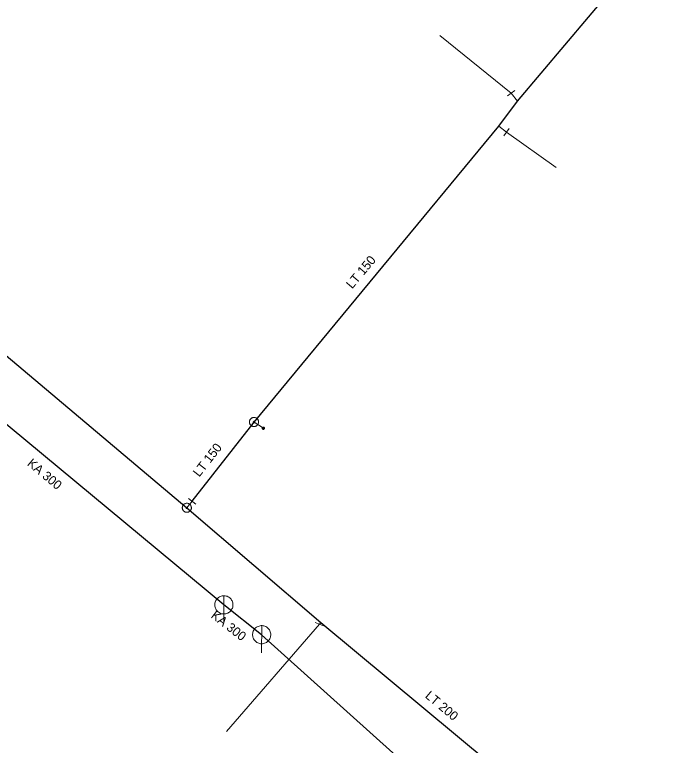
# Model space of a CAD drawing. Extents: x -790267 to -789874, y -989766 to -989454.
# Drawn here: x -790122.7 to -790051.8, y -989692.4 to -989612.1 of the extents above; entities that cross this region are included whole.
import ezdxf

# ---------------------------------------------------------------- set-up
doc = ezdxf.new("R2010")
doc.units = 0
doc.header["$LTSCALE"] = 0.4
doc.layers.add('1', color=7, linetype='Continuous')
for name, color, linetype, lineweight in [('13', 7, 'Continuous', 13), ('14', 7, 'Continuous', 13), ('17', 7, 'Continuous', 25), ('22', 7, 'Continuous', 13), ('34', 7, 'Continuous', 13), ('47', 7, 'Continuous', 13), ('9', 7, 'Continuous', 13)]:
    doc.layers.add(name, color=color, linetype=linetype, lineweight=lineweight)

msp = doc.modelspace()

# ---------------------------------------------------------------- linework, layer by layer
at = {"layer": '13'}
for p, q in [((-790068.059, -989620.701), (-790075.914, -989614.364)), ((-790067.352, -989621.572), (-790068.059, -989620.701)), ((-790089.168, -989679.114), (-790099.39, -989690.91))]:
    msp.add_line(p, q, dxfattribs=at)
msp.add_lwpolyline([(-790069.419, -989624.331), (-790068.577, -989624.976), (-790063.124, -989628.883)], dxfattribs=at)
at = {"layer": '14'}
for p, q in [((-790096.357, -989656.872), (-790095.329, -989657.561)), ((-790103.162, -989665.585), (-790103.748, -989666.305)), ((-790089.02, -989678.91), (-790089.168, -989679.114))]:
    msp.add_line(p, q, dxfattribs=at)
at = {"layer": '14', "lineweight": 25}
msp.add_lwpolyline([(-790061.947, -989710.475), (-790095.515, -989680.27), (-790099.671, -989676.98), (-790135.954, -989646.924), (-790158.92, -989627.239), (-790187.694, -989603.019)], dxfattribs=at)
at = {"layer": '17'}
msp.add_line((-790103.162, -989665.585), (-790096.357, -989656.872), dxfattribs=at)
for points in [[(-790096.357, -989656.872), (-790069.419, -989624.331), (-790067.352, -989621.572), (-790051.752, -989603.049)], [(-790176.006, -989605.454), (-790166.475, -989613.482), (-790103.748, -989666.305)], [(-790103.748, -989666.305), (-790089.02, -989678.91), (-790062.846, -989700.676)]]:
    msp.add_lwpolyline(points, dxfattribs=at)
at = {"layer": '22'}
for p, q in [((-790099.671, -989678.98), (-790099.67, -989675.98)), ((-790095.515, -989682.27), (-790095.514, -989679.27))]:
    msp.add_line(p, q, dxfattribs=at)
for points in [[(-790098.671, -989676.98), (-790098.676, -989676.871), (-790098.694, -989676.763), (-790098.724, -989676.657), (-790098.764, -989676.556), (-790098.816, -989676.459), (-790098.878, -989676.369), (-790098.95, -989676.286), (-790099.03, -989676.212), (-790099.118, -989676.146), (-790099.212, -989676.091), (-790099.312, -989676.046), (-790099.417, -989676.013), (-790099.524, -989675.991), (-790099.633, -989675.981), (-790099.743, -989675.983), (-790099.851, -989675.997), (-790099.958, -989676.022), (-790100.061, -989676.059), (-790100.159, -989676.108), (-790100.251, -989676.166), (-790100.337, -989676.235), (-790100.414, -989676.312), (-790100.483, -989676.398), (-790100.542, -989676.49), (-790100.59, -989676.588), (-790100.627, -989676.691), (-790100.653, -989676.798), (-790100.667, -989676.906), (-790100.67, -989677.016), (-790100.66, -989677.125), (-790100.639, -989677.232), (-790100.605, -989677.336), (-790100.561, -989677.436), (-790100.506, -989677.531), (-790100.44, -989677.619), (-790100.366, -989677.699), (-790100.283, -989677.771), (-790100.193, -989677.833), (-790100.097, -989677.885), (-790099.995, -989677.926), (-790099.89, -989677.956), (-790099.782, -989677.974), (-790099.672, -989677.98), (-790099.563, -989677.974), (-790099.455, -989677.956), (-790099.35, -989677.927), (-790099.248, -989677.886), (-790099.151, -989677.834), (-790099.061, -989677.772), (-790098.978, -989677.701), (-790098.903, -989677.621), (-790098.838, -989677.533), (-790098.782, -989677.439), (-790098.738, -989677.339), (-790098.704, -989677.235), (-790098.682, -989677.127), (-790098.672, -989677.018)], [(-790094.515, -989680.27), (-790094.52, -989680.161), (-790094.538, -989680.053), (-790094.568, -989679.947), (-790094.608, -989679.846), (-790094.66, -989679.749), (-790094.722, -989679.659), (-790094.794, -989679.576), (-790094.874, -989679.502), (-790094.962, -989679.436), (-790095.056, -989679.381), (-790095.156, -989679.336), (-790095.261, -989679.303), (-790095.368, -989679.281), (-790095.477, -989679.271), (-790095.587, -989679.273), (-790095.695, -989679.287), (-790095.802, -989679.312), (-790095.905, -989679.349), (-790096.003, -989679.398), (-790096.095, -989679.456), (-790096.181, -989679.525), (-790096.258, -989679.602), (-790096.327, -989679.688), (-790096.386, -989679.78), (-790096.434, -989679.878), (-790096.471, -989679.981), (-790096.497, -989680.088), (-790096.511, -989680.196), (-790096.514, -989680.306), (-790096.504, -989680.415), (-790096.483, -989680.522), (-790096.449, -989680.626), (-790096.405, -989680.726), (-790096.35, -989680.821), (-790096.284, -989680.909), (-790096.21, -989680.989), (-790096.127, -989681.061), (-790096.037, -989681.123), (-790095.941, -989681.175), (-790095.839, -989681.216), (-790095.734, -989681.246), (-790095.626, -989681.264), (-790095.516, -989681.27), (-790095.407, -989681.264), (-790095.299, -989681.246), (-790095.194, -989681.217), (-790095.092, -989681.176), (-790094.995, -989681.124), (-790094.905, -989681.062), (-790094.822, -989680.991), (-790094.747, -989680.911), (-790094.682, -989680.823), (-790094.626, -989680.729), (-790094.582, -989680.629), (-790094.548, -989680.525), (-790094.526, -989680.417), (-790094.516, -989680.308)]]:
    msp.add_lwpolyline(points, close=True, dxfattribs=at)
at = {"layer": '34'}
for p, q in [((-790067.649, -989620.414), (-790068.469, -989620.987)), ((-790068.275, -989624.577), (-790068.879, -989625.374)), ((-790103.549, -989665.268), (-790102.775, -989665.902)), ((-790089.636, -989678.938), (-790088.7, -989679.29))]:
    msp.add_line(p, q, dxfattribs=at)
at = {"layer": '47'}
for points in [[(-790096.037, -989656.487), (-790096.079, -989656.456), (-790096.124, -989656.429), (-790096.172, -989656.408), (-790096.221, -989656.39), (-790096.273, -989656.379), (-790096.325, -989656.373), (-790096.377, -989656.373), (-790096.429, -989656.378), (-790096.48, -989656.387), (-790096.53, -989656.403), (-790096.579, -989656.424), (-790096.624, -989656.45), (-790096.667, -989656.479), (-790096.706, -989656.514), (-790096.741, -989656.552), (-790096.772, -989656.594), (-790096.799, -989656.639), (-790096.821, -989656.688), (-790096.838, -989656.736), (-790096.849, -989656.788), (-790096.855, -989656.84), (-790096.856, -989656.893), (-790096.851, -989656.945), (-790096.841, -989656.996), (-790096.825, -989657.045), (-790096.804, -989657.094), (-790096.779, -989657.14), (-790096.749, -989657.182), (-790096.714, -989657.221), (-790096.676, -989657.256), (-790096.634, -989657.287), (-790096.589, -989657.314), (-790096.541, -989657.337), (-790096.492, -989657.353), (-790096.44, -989657.364), (-790096.389, -989657.371), (-790096.336, -989657.372), (-790096.284, -989657.367), (-790096.232, -989657.356), (-790096.183, -989657.34), (-790096.134, -989657.319), (-790096.089, -989657.295), (-790096.046, -989657.264), (-790096.007, -989657.229), (-790095.972, -989657.191), (-790095.941, -989657.149), (-790095.914, -989657.104), (-790095.892, -989657.057), (-790095.875, -989657.007), (-790095.864, -989656.955), (-790095.857, -989656.904), (-790095.857, -989656.852), (-790095.862, -989656.8), (-790095.872, -989656.748), (-790095.888, -989656.698), (-790095.909, -989656.649), (-790095.934, -989656.605), (-790095.964, -989656.561), (-790095.999, -989656.522)], [(-790096.304, -989656.808), (-790096.311, -989656.803), (-790096.319, -989656.799), (-790096.326, -989656.795), (-790096.334, -989656.793), (-790096.343, -989656.791), (-790096.351, -989656.79), (-790096.36, -989656.789), (-790096.368, -989656.79), (-790096.377, -989656.792), (-790096.385, -989656.795), (-790096.393, -989656.798), (-790096.401, -989656.802), (-790096.407, -989656.807), (-790096.414, -989656.812), (-790096.42, -989656.819), (-790096.425, -989656.826), (-790096.429, -989656.834), (-790096.433, -989656.841), (-790096.435, -989656.849), (-790096.437, -989656.858), (-790096.438, -989656.866), (-790096.439, -989656.875), (-790096.438, -989656.883), (-790096.436, -989656.892), (-790096.433, -989656.9), (-790096.43, -989656.908), (-790096.426, -989656.916), (-790096.421, -989656.922), (-790096.416, -989656.929), (-790096.409, -989656.935), (-790096.402, -989656.94), (-790096.394, -989656.944), (-790096.387, -989656.948), (-790096.379, -989656.95), (-790096.37, -989656.952), (-790096.362, -989656.954), (-790096.353, -989656.954), (-790096.345, -989656.953), (-790096.336, -989656.951), (-790096.328, -989656.948), (-790096.32, -989656.945), (-790096.312, -989656.941), (-790096.306, -989656.936), (-790096.299, -989656.931), (-790096.293, -989656.924), (-790096.288, -989656.917), (-790096.284, -989656.909), (-790096.28, -989656.902), (-790096.278, -989656.894), (-790096.276, -989656.885), (-790096.274, -989656.877), (-790096.274, -989656.868), (-790096.275, -989656.86), (-790096.277, -989656.851), (-790096.28, -989656.843), (-790096.283, -989656.835), (-790096.287, -989656.827), (-790096.292, -989656.821), (-790096.297, -989656.814)], [(-790103.358, -989666.618), (-790103.328, -989666.575), (-790103.301, -989666.53), (-790103.281, -989666.482), (-790103.264, -989666.433), (-790103.253, -989666.381), (-790103.248, -989666.328), (-790103.249, -989666.277), (-790103.255, -989666.225), (-790103.265, -989666.174), (-790103.281, -989666.124), (-790103.303, -989666.075), (-790103.33, -989666.031), (-790103.36, -989665.989), (-790103.396, -989665.95), (-790103.434, -989665.915), (-790103.477, -989665.885), (-790103.522, -989665.858), (-790103.571, -989665.837), (-790103.619, -989665.821), (-790103.671, -989665.81), (-790103.724, -989665.805), (-790103.776, -989665.805), (-790103.828, -989665.811), (-790103.879, -989665.822), (-790103.928, -989665.838), (-790103.977, -989665.86), (-790104.022, -989665.886), (-790104.063, -989665.917), (-790104.102, -989665.953), (-790104.137, -989665.991), (-790104.167, -989666.034), (-790104.194, -989666.079), (-790104.216, -989666.127), (-790104.231, -989666.176), (-790104.242, -989666.228), (-790104.247, -989666.28), (-790104.247, -989666.333), (-790104.242, -989666.385), (-790104.23, -989666.436), (-790104.214, -989666.485), (-790104.192, -989666.534), (-790104.167, -989666.578), (-790104.135, -989666.62), (-790104.099, -989666.659), (-790104.061, -989666.694), (-790104.018, -989666.724), (-790103.973, -989666.751), (-790103.926, -989666.772), (-790103.876, -989666.788), (-790103.824, -989666.799), (-790103.772, -989666.804), (-790103.72, -989666.804), (-790103.668, -989666.798), (-790103.617, -989666.787), (-790103.567, -989666.771), (-790103.518, -989666.749), (-790103.474, -989666.723), (-790103.432, -989666.692), (-790103.393, -989666.656)], [(-790103.684, -989666.356), (-790103.678, -989666.349), (-790103.674, -989666.341), (-790103.671, -989666.334), (-790103.668, -989666.326), (-790103.666, -989666.317), (-790103.666, -989666.308), (-790103.665, -989666.3), (-790103.666, -989666.291), (-790103.669, -989666.283), (-790103.671, -989666.275), (-790103.675, -989666.267), (-790103.679, -989666.259), (-790103.684, -989666.253), (-790103.689, -989666.246), (-790103.696, -989666.241), (-790103.703, -989666.235), (-790103.711, -989666.231), (-790103.718, -989666.228), (-790103.726, -989666.225), (-790103.735, -989666.223), (-790103.744, -989666.223), (-790103.752, -989666.222), (-790103.761, -989666.223), (-790103.77, -989666.225), (-790103.777, -989666.228), (-790103.785, -989666.232), (-790103.793, -989666.236), (-790103.799, -989666.241), (-790103.806, -989666.246), (-790103.811, -989666.253), (-790103.817, -989666.26), (-790103.821, -989666.268), (-790103.824, -989666.275), (-790103.827, -989666.283), (-790103.829, -989666.292), (-790103.83, -989666.3), (-790103.83, -989666.309), (-790103.829, -989666.318), (-790103.827, -989666.327), (-790103.824, -989666.334), (-790103.82, -989666.342), (-790103.816, -989666.35), (-790103.811, -989666.356), (-790103.806, -989666.363), (-790103.799, -989666.368), (-790103.792, -989666.374), (-790103.784, -989666.378), (-790103.777, -989666.381), (-790103.769, -989666.384), (-790103.76, -989666.386), (-790103.752, -989666.387), (-790103.743, -989666.387), (-790103.734, -989666.386), (-790103.726, -989666.383), (-790103.718, -989666.381), (-790103.71, -989666.377), (-790103.702, -989666.373), (-790103.696, -989666.368), (-790103.689, -989666.363)]]:
    msp.add_lwpolyline(points, close=True, dxfattribs=at)
at = {"layer": '9'}
for points in [[(-790095.455, -989657.561), (-790095.455, -989657.574), (-790095.453, -989657.587), (-790095.45, -989657.6), (-790095.445, -989657.612), (-790095.439, -989657.624), (-790095.432, -989657.635), (-790095.424, -989657.645), (-790095.414, -989657.655), (-790095.404, -989657.663), (-790095.393, -989657.67), (-790095.381, -989657.676), (-790095.369, -989657.681), (-790095.356, -989657.684), (-790095.343, -989657.686), (-790095.33, -989657.688), (-790095.317, -989657.687), (-790095.304, -989657.685), (-790095.291, -989657.682), (-790095.279, -989657.677), (-790095.267, -989657.671), (-790095.256, -989657.664), (-790095.246, -989657.656), (-790095.236, -989657.646), (-790095.228, -989657.636), (-790095.221, -989657.625), (-790095.215, -989657.613), (-790095.21, -989657.601), (-790095.207, -989657.588), (-790095.205, -989657.575), (-790095.203, -989657.562), (-790095.204, -989657.549), (-790095.206, -989657.536), (-790095.209, -989657.523), (-790095.214, -989657.511), (-790095.22, -989657.499), (-790095.227, -989657.488), (-790095.235, -989657.478), (-790095.245, -989657.468), (-790095.255, -989657.46), (-790095.266, -989657.453), (-790095.278, -989657.447), (-790095.29, -989657.442), (-790095.303, -989657.439), (-790095.316, -989657.437), (-790095.329, -989657.436), (-790095.342, -989657.436), (-790095.355, -989657.438), (-790095.368, -989657.441), (-790095.38, -989657.446), (-790095.392, -989657.452), (-790095.403, -989657.459), (-790095.413, -989657.467), (-790095.423, -989657.477), (-790095.431, -989657.487), (-790095.438, -989657.498), (-790095.444, -989657.51), (-790095.449, -989657.522), (-790095.452, -989657.535), (-790095.454, -989657.548)], [(-790095.435, -989657.561), (-790095.436, -989657.572), (-790095.434, -989657.583), (-790095.431, -989657.594), (-790095.427, -989657.604), (-790095.422, -989657.614), (-790095.416, -989657.623), (-790095.409, -989657.632), (-790095.401, -989657.64), (-790095.392, -989657.647), (-790095.383, -989657.653), (-790095.373, -989657.658), (-790095.363, -989657.662), (-790095.352, -989657.665), (-790095.341, -989657.668), (-790095.33, -989657.668), (-790095.319, -989657.668), (-790095.308, -989657.666), (-790095.297, -989657.663), (-790095.287, -989657.659), (-790095.277, -989657.654), (-790095.268, -989657.648), (-790095.259, -989657.641), (-790095.251, -989657.633), (-790095.244, -989657.624), (-790095.238, -989657.615), (-790095.233, -989657.605), (-790095.229, -989657.595), (-790095.226, -989657.584), (-790095.224, -989657.573), (-790095.223, -989657.562), (-790095.223, -989657.551), (-790095.225, -989657.54), (-790095.228, -989657.529), (-790095.232, -989657.519), (-790095.237, -989657.509), (-790095.243, -989657.5), (-790095.25, -989657.491), (-790095.258, -989657.483), (-790095.267, -989657.476), (-790095.276, -989657.47), (-790095.286, -989657.465), (-790095.296, -989657.461), (-790095.307, -989657.458), (-790095.318, -989657.456), (-790095.329, -989657.456), (-790095.34, -989657.455), (-790095.351, -989657.457), (-790095.362, -989657.46), (-790095.372, -989657.464), (-790095.382, -989657.469), (-790095.391, -989657.475), (-790095.4, -989657.482), (-790095.408, -989657.49), (-790095.415, -989657.499), (-790095.421, -989657.508), (-790095.426, -989657.518), (-790095.43, -989657.528), (-790095.433, -989657.539), (-790095.435, -989657.55)], [(-790095.416, -989657.561), (-790095.416, -989657.57), (-790095.415, -989657.579), (-790095.412, -989657.588), (-790095.409, -989657.596), (-790095.405, -989657.604), (-790095.4, -989657.612), (-790095.394, -989657.619), (-790095.388, -989657.625), (-790095.381, -989657.631), (-790095.373, -989657.636), (-790095.365, -989657.64), (-790095.357, -989657.643), (-790095.348, -989657.646), (-790095.339, -989657.647), (-790095.33, -989657.649), (-790095.321, -989657.648), (-790095.312, -989657.647), (-790095.303, -989657.644), (-790095.295, -989657.641), (-790095.287, -989657.637), (-790095.279, -989657.632), (-790095.272, -989657.626), (-790095.266, -989657.62), (-790095.26, -989657.613), (-790095.255, -989657.605), (-790095.251, -989657.597), (-790095.248, -989657.589), (-790095.245, -989657.58), (-790095.244, -989657.571), (-790095.242, -989657.562), (-790095.243, -989657.553), (-790095.244, -989657.544), (-790095.247, -989657.535), (-790095.25, -989657.527), (-790095.254, -989657.519), (-790095.259, -989657.511), (-790095.265, -989657.504), (-790095.271, -989657.498), (-790095.278, -989657.492), (-790095.286, -989657.487), (-790095.294, -989657.483), (-790095.302, -989657.48), (-790095.311, -989657.477), (-790095.32, -989657.476), (-790095.329, -989657.475), (-790095.338, -989657.475), (-790095.347, -989657.476), (-790095.356, -989657.479), (-790095.364, -989657.482), (-790095.372, -989657.486), (-790095.38, -989657.491), (-790095.387, -989657.497), (-790095.393, -989657.503), (-790095.399, -989657.51), (-790095.404, -989657.518), (-790095.408, -989657.526), (-790095.411, -989657.534), (-790095.414, -989657.543), (-790095.415, -989657.552)], [(-790095.396, -989657.561), (-790095.396, -989657.568), (-790095.395, -989657.575), (-790095.394, -989657.582), (-790095.391, -989657.588), (-790095.388, -989657.594), (-790095.384, -989657.6), (-790095.38, -989657.606), (-790095.375, -989657.611), (-790095.369, -989657.615), (-790095.363, -989657.619), (-790095.357, -989657.622), (-790095.351, -989657.625), (-790095.344, -989657.626), (-790095.337, -989657.629), (-790095.33, -989657.629), (-790095.323, -989657.629), (-790095.316, -989657.627), (-790095.309, -989657.626), (-790095.303, -989657.623), (-790095.296, -989657.62), (-790095.291, -989657.616), (-790095.285, -989657.612), (-790095.28, -989657.607), (-790095.276, -989657.601), (-790095.272, -989657.595), (-790095.269, -989657.589), (-790095.266, -989657.583), (-790095.264, -989657.576), (-790095.263, -989657.569), (-790095.262, -989657.562), (-790095.262, -989657.555), (-790095.263, -989657.548), (-790095.265, -989657.541), (-790095.268, -989657.535), (-790095.271, -989657.528), (-790095.275, -989657.523), (-790095.279, -989657.517), (-790095.284, -989657.512), (-790095.29, -989657.508), (-790095.295, -989657.504), (-790095.302, -989657.501), (-790095.308, -989657.498), (-790095.315, -989657.496), (-790095.322, -989657.495), (-790095.329, -989657.495), (-790095.336, -989657.495), (-790095.343, -989657.495), (-790095.35, -989657.497), (-790095.356, -989657.5), (-790095.362, -989657.503), (-790095.368, -989657.507), (-790095.374, -989657.511), (-790095.379, -989657.516), (-790095.383, -989657.522), (-790095.387, -989657.527), (-790095.39, -989657.534), (-790095.393, -989657.54), (-790095.394, -989657.547), (-790095.396, -989657.554)], [(-790095.376, -989657.561), (-790095.376, -989657.566), (-790095.376, -989657.571), (-790095.375, -989657.576), (-790095.373, -989657.58), (-790095.371, -989657.585), (-790095.368, -989657.589), (-790095.365, -989657.592), (-790095.361, -989657.596), (-790095.358, -989657.599), (-790095.354, -989657.602), (-790095.349, -989657.604), (-790095.345, -989657.606), (-790095.34, -989657.607), (-790095.335, -989657.609), (-790095.33, -989657.609), (-790095.325, -989657.609), (-790095.32, -989657.608), (-790095.315, -989657.607), (-790095.311, -989657.605), (-790095.306, -989657.603), (-790095.302, -989657.6), (-790095.298, -989657.597), (-790095.295, -989657.593), (-790095.292, -989657.59), (-790095.289, -989657.586), (-790095.287, -989657.581), (-790095.285, -989657.577), (-790095.284, -989657.572), (-790095.283, -989657.567), (-790095.282, -989657.562), (-790095.282, -989657.557), (-790095.283, -989657.552), (-790095.284, -989657.547), (-790095.286, -989657.543), (-790095.288, -989657.538), (-790095.291, -989657.534), (-790095.294, -989657.53), (-790095.297, -989657.527), (-790095.301, -989657.524), (-790095.305, -989657.521), (-790095.31, -989657.519), (-790095.314, -989657.517), (-790095.319, -989657.516), (-790095.324, -989657.515), (-790095.329, -989657.515), (-790095.334, -989657.515), (-790095.339, -989657.516), (-790095.344, -989657.516), (-790095.348, -989657.518), (-790095.353, -989657.52), (-790095.357, -989657.523), (-790095.36, -989657.526), (-790095.364, -989657.529), (-790095.367, -989657.533), (-790095.37, -989657.537), (-790095.372, -989657.542), (-790095.374, -989657.546), (-790095.375, -989657.551), (-790095.376, -989657.556)], [(-790095.356, -989657.561), (-790095.356, -989657.564), (-790095.357, -989657.567), (-790095.356, -989657.569), (-790095.355, -989657.572), (-790095.354, -989657.575), (-790095.352, -989657.577), (-790095.35, -989657.579), (-790095.348, -989657.581), (-790095.346, -989657.583), (-790095.344, -989657.585), (-790095.341, -989657.587), (-790095.338, -989657.588), (-790095.336, -989657.588), (-790095.333, -989657.589), (-790095.33, -989657.589), (-790095.327, -989657.589), (-790095.324, -989657.589), (-790095.321, -989657.588), (-790095.319, -989657.587), (-790095.316, -989657.586), (-790095.314, -989657.584), (-790095.311, -989657.582), (-790095.309, -989657.58), (-790095.308, -989657.578), (-790095.306, -989657.576), (-790095.305, -989657.573), (-790095.303, -989657.57), (-790095.303, -989657.568), (-790095.302, -989657.565), (-790095.301, -989657.562), (-790095.302, -989657.559), (-790095.302, -989657.556), (-790095.303, -989657.553), (-790095.304, -989657.551), (-790095.305, -989657.548), (-790095.307, -989657.546), (-790095.308, -989657.543), (-790095.31, -989657.541), (-790095.313, -989657.54), (-790095.315, -989657.538), (-790095.318, -989657.537), (-790095.32, -989657.536), (-790095.323, -989657.535), (-790095.326, -989657.535), (-790095.329, -989657.534), (-790095.332, -989657.535), (-790095.335, -989657.534), (-790095.337, -989657.536), (-790095.34, -989657.536), (-790095.343, -989657.537), (-790095.345, -989657.539), (-790095.347, -989657.54), (-790095.349, -989657.542), (-790095.351, -989657.545), (-790095.353, -989657.547), (-790095.354, -989657.55), (-790095.355, -989657.552), (-790095.356, -989657.555), (-790095.356, -989657.558)], [(-790095.337, -989657.561), (-790095.337, -989657.563), (-790095.337, -989657.563), (-790095.336, -989657.563), (-790095.336, -989657.565), (-790095.337, -989657.566), (-790095.335, -989657.566), (-790095.335, -989657.566), (-790095.335, -989657.568), (-790095.335, -989657.568), (-790095.334, -989657.569), (-790095.332, -989657.569), (-790095.332, -989657.569), (-790095.332, -989657.57), (-790095.33, -989657.57), (-790095.33, -989657.57), (-790095.329, -989657.57), (-790095.328, -989657.57), (-790095.328, -989657.569), (-790095.327, -989657.569), (-790095.325, -989657.569), (-790095.325, -989657.568), (-790095.325, -989657.568), (-790095.324, -989657.567), (-790095.324, -989657.567), (-790095.322, -989657.566), (-790095.322, -989657.565), (-790095.321, -989657.564), (-790095.321, -989657.564), (-790095.321, -989657.563), (-790095.321, -989657.562), (-790095.321, -989657.561), (-790095.321, -989657.56), (-790095.321, -989657.56), (-790095.322, -989657.559), (-790095.322, -989657.558), (-790095.323, -989657.557), (-790095.323, -989657.557), (-790095.324, -989657.556), (-790095.324, -989657.556), (-790095.325, -989657.555), (-790095.326, -989657.555), (-790095.327, -989657.554), (-790095.327, -989657.554), (-790095.328, -989657.554), (-790095.329, -989657.554), (-790095.33, -989657.554), (-790095.331, -989657.554), (-790095.331, -989657.554), (-790095.332, -989657.555), (-790095.333, -989657.554), (-790095.334, -989657.556), (-790095.334, -989657.556), (-790095.335, -989657.556), (-790095.335, -989657.556), (-790095.336, -989657.558), (-790095.336, -989657.559), (-790095.336, -989657.56), (-790095.337, -989657.56), (-790095.337, -989657.561)]]:
    msp.add_lwpolyline(points, close=True, dxfattribs=at)

# ---------------------------------------------------------------- texts
at = {"layer": '1'}
for s, rotation, p in [('LT 150', 50, (-790085.559, -989642.284)), ('LT 150', 52, (-790102.382, -989662.985)), ('KA 300', 320, (-790121.389, -989661.567)), ('KA 300', 322, (-790101.177, -989678.318)), ('LT 200', 320, (-790077.609, -989687.117))]:
    msp.add_text(s, height=1, rotation=rotation, dxfattribs=at).set_placement(p)

doc.saveas('drawing.dxf')
